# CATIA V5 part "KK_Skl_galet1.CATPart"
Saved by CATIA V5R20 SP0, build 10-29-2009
Part number: Skl_galet1
Publications: "Axe_pivot_galet1", "Plan.Ref5", "Point.2", "Plan_Ref1"
Bounding box of the stored display mesh (mm): x -7.5 to 32.5, y 175 to 175, z -15 to -15
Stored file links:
  G:\Khaled_CFAO_2011\ST2M\ST2M_GR2\aandujar\Khaled\CAD_thinkMOTION\KK_Skl_galet1.CATPart
  G:\Khaled_CFAO_2011\ST2M\ST2M_GR2\aandujar\Khaled\CAD_thinkMOTION\KK_Skl_scie_mecanique.CATProduct
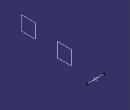
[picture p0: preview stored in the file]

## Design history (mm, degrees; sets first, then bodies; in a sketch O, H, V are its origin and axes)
WSupportSet1: ActiveGrid {3dwsupport RefPoint {point stored without definition}, 3DWOS ({wsupport Support xy-plane, RefPoint {3dwsupport}, GridIn {cartgrid Value 100, Stepbid1 0, Value 100, Stepbid2 0, Direction (1, 0, 0)}, GeometricData ({line type PtDir, Direction (1, 0, 0), Support xy-plane}; {line type PtDir, Direction (0, 1, 0), Support yz-plane})}; {wsupport Support yz-plane, RefPoint {3dwsupport}, GridIn {cartgrid Value 100, Stepbid1 0, Value 100, Stepbid2 0, Direction (0, 1, 0)}, GeometricData ({line type PtDir, Direction (0, 1, 0), Support yz-plane}; {line type PtDir, Direction (0, 0, 1), Support zx-plane})}; {wsupport Support zx-plane, RefPoint {3dwsupport}, GridIn {cartgrid Value 100, Stepbid1 0, Value 100, Stepbid2 0, Direction (0, 0, 1)}, GeometricData ({line type PtDir, Direction (0, 0, 1), Support zx-plane}; {line type PtDir, Direction (1, 0, 0), Support xy-plane})}), GeometricData ({line type PtDir, RefPoint {point stored without definition}, Direction (1, 0, 0), Support xy-plane}; {line type PtDir, RefPoint {point stored without definition}, Direction (0, 1, 0), Support yz-plane}; {line type PtDir, RefPoint {point stored without definition}, Direction (0, 0, 1), Support zx-plane})}
Set1
  Line1 "Axe_pivot_galet1": type Normal, RefPoint Point1, RefSkin Plane2, Start -20, End 20
Set2
  Plane1 "Plan.Ref5": linked copy from another document
  Point1: linked copy from another document
  Plane2 "Plan_Ref1": linked copy from another document
Body1 (main body)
